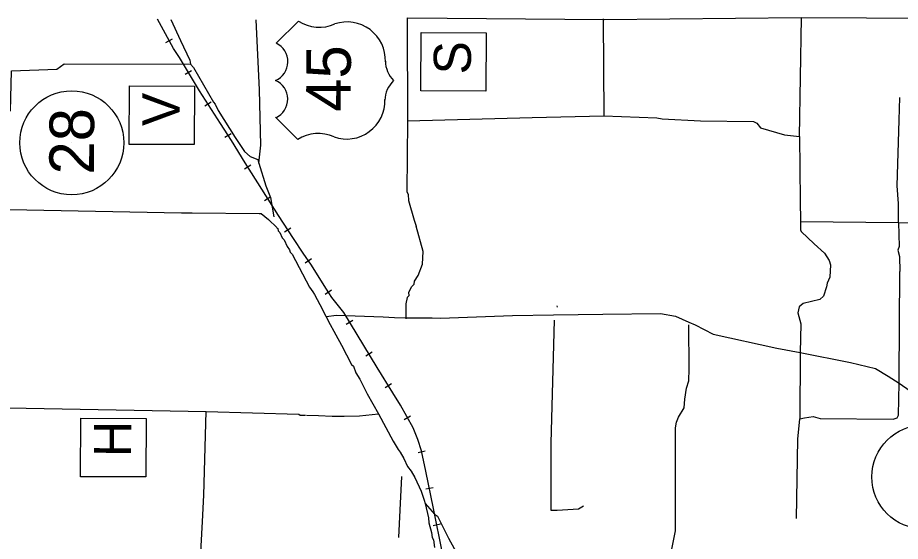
# Model space of a CAD drawing. Extents: x 299354 to 1325680, y 96128 to 228242.
# Drawn here: x 341858 to 365592, y 213706 to 227778 of the extents above; entities that cross this region are included whole.
import ezdxf

# ---------------------------------------------------------------- set-up
doc = ezdxf.new("R2010")
doc.units = 0
for name, color, linetype in [('Level 12', 7, 'Continuous'), ('Level 13', 7, 'Continuous'), ('Level 2', 7, 'Continuous'), ('Level 4', 7, 'Continuous'), ('Level 45', 7, 'Continuous')]:
    doc.layers.add(name, color=color, linetype=linetype)

msp = doc.modelspace()

# ---------------------------------------------------------------- linework, layer by layer
at = {"layer": 'Level 12'}
for p, q in [((348810, 227091), (349410, 227686)), ((350216, 226130), (350216, 226130)), ((348793, 225104), (349387, 224504)), ((343313, 224416), (343313, 224416))]:
    msp.add_line(p, q, dxfattribs=at)
for centre in [(343313, 224416), (366223, 215436)]:
    msp.add_circle(centre, 1398, dxfattribs=at)
for centre, radius, start, end in [((349969, 228550), 1030, 237.0806, 293.9627), ((350716, 226633), 1030, 357.5765, 108.6722), ((348577, 226595), 548, 292.8862, 64.8376), ((352500, 226623), 755, 181.0102, 225.044), ((348573, 225587), 548, 294.6963, 66.6477), ((352487, 225542), 755, 133.5398, 178.5237), ((350702, 225546), 1030, 250.8617, 1.9574), ((349940, 223635), 1030, 65.5713, 122.4533)]:
    msp.add_arc(centre, radius, start, end, dxfattribs=at)
at = {"layer": 'Level 13'}
for p, q in [((353556, 226626), (353556, 226626)), ((345712, 225188), (345712, 225188)), ((344408, 216258), (344408, 216258))]:
    msp.add_line(p, q, dxfattribs=at)
for points in [[(354449, 225804), (352699, 225812), (352706, 227382), (354456, 227374)], [(346606, 224366), (344856, 224373), (344862, 225943), (346612, 225936)], [(345302, 215436), (343552, 215443), (343559, 217013), (345309, 217006)]]:
    msp.add_lwpolyline(points, close=True, dxfattribs=at)
at = {"layer": 'Level 2'}
for points in [[(345977, 227728), (346236, 227163), (346489, 226636), (346505, 226527)], [(348345, 223872), (348395, 224352), (348358, 225837), (348274, 227724)], [(352330, 227773), (352329, 227668), (352338, 225008)], [(346505, 226527), (346588, 226443), (347121, 225504), (347171, 225454), (347253, 225286), (347705, 224557), (347960, 224180), (348109, 224045), (348317, 223968), (348345, 223872)], [(352338, 225008), (352321, 223107), (352354, 223024), (352369, 222865), (352522, 222339)], [(348345, 223872), (348527, 223257), (348658, 222948), (348745, 222430)], [(306377, 222972), (306911, 222975), (308905, 222983), (311733, 222991), (312266, 222986), (314935, 222954), (317579, 222914), (318313, 222900), (320231, 222858), (322933, 222800), (325451, 222736), (325618, 222735), (330998, 222679), (331757, 222664), (333333, 222667), (336294, 222657), (340790, 222634), (341640, 222626), (346260, 222536), (346552, 222533), (348354, 222517)], [(348354, 222517), (348404, 222517), (348603, 222356), (348826, 222137)], [(352516, 220621), (352525, 220696), (352626, 220853), (352746, 221152), (352765, 221494), (352571, 222171)], [(352522, 222339), (352571, 222171)], [(348830, 222132), (348851, 222112), (348867, 222054), (348908, 222004), (348974, 221861), (349023, 221811), (349105, 221627), (349171, 221543), (349187, 221476), (349237, 221425), (349704, 220537), (349795, 220412), (349836, 220336), (349983, 220068), (350098, 219850), (350139, 219767), (350157, 219745)], [(352388, 220314), (352380, 220397), (352448, 220546), (352516, 220621)], [(352388, 220314), (352329, 220256), (352294, 220089), (352299, 219714), (352297, 219686)], [(350157, 219745), (350431, 219781), (351682, 219736), (351990, 219717), (352299, 219714), (352616, 219711), (353000, 219708), (353225, 219706), (355160, 219772), (356262, 219796), (357588, 219809), (359140, 219829), (359548, 219758), (359905, 219597), (360071, 219520), (360561, 219274), (362268, 218900), (362900, 218778), (364249, 218508), (364923, 218352), (365264, 218149), (365562, 217954), (365852, 217752)], [(350157, 219745), (350205, 219633), (350410, 219256), (350566, 218979), (350836, 218460), (350886, 218409), (350951, 218234), (351058, 218066), (351255, 217672), (351558, 217136), (351952, 216399), (352092, 216172), (352141, 216105), (352240, 215929), (352338, 215720), (352437, 215594), (352535, 215418), (352707, 215050), (352789, 214816), (352813, 214724), (352901, 214339), (352917, 214206), (352989, 213947), (353005, 213813), (353038, 213746), (353069, 213537)], [(341601, 217291), (346930, 217194)], [(346930, 217194), (349415, 217122), (349456, 217096), (349598, 217095)], [(349623, 217095), (349948, 217092)], [(349948, 217092), (350315, 217072)], [(350315, 217072), (350640, 217069)], [(350640, 217069), (351049, 217082)], [(351049, 217082), (351216, 217097), (351558, 217136)]]:
    msp.add_lwpolyline(points, dxfattribs=at)
at = {"layer": 'Level 4'}
for p, q in [((345844, 227115), (346019, 227212)), ((346363, 226256), (346534, 226360)), ((346895, 225406), (347063, 225514)), ((347431, 224563), (347601, 224669)), ((347960, 223714), (348129, 223821)), ((348495, 222869), (348664, 222976)), ((349035, 222026), (349202, 222135)), ((349592, 221191), (349755, 221307)), ((350129, 220352), (350296, 220462)), ((350695, 219546), (350866, 219650)), ((351218, 218693), (351388, 218798)), ((351742, 217841), (351912, 217946)), ((352247, 216984), (352423, 217081)), ((352624, 216092), (352819, 216136)), ((352832, 215116), (353028, 215156)), ((353031, 214136), (353227, 214176))]:
    msp.add_line(p, q, dxfattribs=at)
for points in [[(346206, 226705), (346050, 226948), (345615, 227735)], [(353285, 213386), (353041, 214591), (352837, 215591), (352717, 216134), (352620, 216443), (352489, 216753), (352153, 217364), (351947, 217699), (351528, 218379), (350624, 219854), (350619, 219855), (350624, 219854), (350310, 220257), (350228, 220383), (350096, 220584), (349759, 221129), (349533, 221446), (349274, 221842), (348871, 222462), (347974, 223879), (347604, 224475), (347316, 224936), (346749, 225816), (346206, 226705), (346050, 226948), (345615, 227735)], [(357628, 227722), (352345, 227763)], [(357603, 227750), (357619, 225136)], [(362929, 227772), (357628, 227722)], [(362878, 224581), (362938, 227778)], [(368194, 227744), (362929, 227772)], [(347974, 223879), (347604, 224475), (347316, 224936), (346749, 225816), (346206, 226705)], [(341664, 225269), (341691, 226353), (342909, 226392), (343110, 226540), (346505, 226527)], [(365543, 222273), (365539, 222782), (365510, 223257), (365559, 225024), (365581, 225633)], [(352338, 225008), (355692, 225095), (357619, 225136)], [(357619, 225136), (359045, 225090), (359187, 225064), (360221, 225005), (361647, 224992)], [(361647, 224992), (361730, 224942), (361829, 224816), (362478, 224626), (362878, 224581)], [(362878, 224581), (362896, 222864), (362907, 222305)], [(349533, 221446), (349274, 221842), (348871, 222462), (347974, 223879)], [(362907, 222305), (362905, 222080), (362921, 222030), (363277, 221701), (363550, 221449), (363682, 221256), (363714, 221139), (363694, 220805), (363626, 220648), (363609, 220548), (363523, 220298), (363430, 220207), (362979, 220095), (362870, 220012), (362835, 219846), (362916, 219553), (362900, 218778), (362893, 217002)], [(362907, 222305), (365543, 222273)], [(365543, 222273), (365562, 221631), (365528, 221531), (365568, 221364), (365581, 220956)], [(365543, 222273), (367077, 222260), (367152, 222176), (367301, 222124), (367418, 222123), (367728, 222254), (368203, 222258)], [(349759, 221129), (349533, 221446)], [(350619, 219855), (350624, 219854), (350310, 220257), (350228, 220383), (350096, 220584), (349759, 221129)], [(362893, 217002), (363018, 217026), (363252, 217058), (363435, 217006), (365403, 216988), (365504, 217021), (365546, 217096), (365562, 217954), (365563, 218096), (365581, 220956)], [(351528, 218379), (350624, 219854)], [(356282, 219649), (356197, 216345), (356198, 214544), (356364, 214542), (356940, 214579), (357075, 214661)], [(359550, 216758), (359572, 216907), (359623, 217040), (359776, 217297), (359795, 217530), (359839, 217821), (359907, 218021), (359910, 218346), (359904, 219522)], [(352837, 215591), (352717, 216134), (352620, 216443), (352489, 216753), (352153, 217364), (351947, 217699), (351528, 218379)], [(346701, 211921), (346826, 214237), (346868, 214947), (346930, 217194)], [(362798, 214323), (362836, 216452), (362893, 217002)], [(359266, 212121), (359400, 212585), (359406, 212961), (359393, 213228), (359550, 213986), (359550, 216758)], [(353041, 214591), (352837, 215591)], [(352104, 213810), (352140, 214544), (352185, 215446)], [(352813, 214724), (353062, 214433), (353146, 214381), (353444, 213794), (354158, 212484), (354257, 212323), (354357, 212102)], [(353501, 212408), (353396, 212843), (353285, 213386), (353041, 214591)]]:
    msp.add_lwpolyline(points, dxfattribs=at)
at = {"layer": 'Level 45'}
msp.add_lwpolyline([(356358, 220031), (356367, 219997)], dxfattribs=at)

# ---------------------------------------------------------------- texts
at = {"layer": 'Level 12'}
for s, p in [('45', (350813, 225249)), ('28', (343909, 223561))]:
    msp.add_text(s, height=1200, rotation=89.767, dxfattribs=at).set_placement(p)
at = {"layer": 'Level 13'}
for s, p in [('S', (354045, 226252)), ('V', (346211, 224863)), ('H', (344907, 215972))]:
    msp.add_text(s, height=1000, rotation=89.767, dxfattribs=at).set_placement(p)

doc.saveas('drawing.dxf')
